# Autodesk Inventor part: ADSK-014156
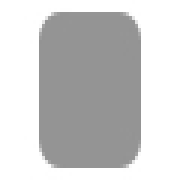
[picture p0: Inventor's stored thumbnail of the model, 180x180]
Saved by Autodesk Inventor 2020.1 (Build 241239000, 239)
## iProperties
Created: 2019-01
Part Number: ADSK-014156
Material: Stahl, weich
Document SubType Name: Modeling
Designer: lutzd
Language: de-DE
Size Designation: 5 x 39,384472 x 39,384472
Categories: <MemberInstance><Categories><Category DisplayName="Sonstige Bauteile" InternalName="5aa15e00-363f-49f2-933f-16f664388e3f" Mnemonic="OTHER"><Category DisplayName
Mass: 60.0398 g
Surface Area: 38.0412 cm^2
Volume: 7.64838 cm^3
Density: 7.85 g/cm^3
Appearance: Halbpoliert
IsCustomPart: 1
Title: end cap
Author: lutzd
Revision Number: -
Dimensions: 39,4x39,4x5 mm
Mass: 0,06 kg
DocNumber: ADSK-014156
Folder: 01 - Themengebiete\Simplification\01 - Packaging machine\
VDS_Category: 3D Komponenten
VDS_NumSchm: Autodesk
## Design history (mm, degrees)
sketch "Sketch1"
  geometry: L1 (0, 20.175)-(0, -21.446); L2 (-20.203, 0)-(20.169, 0); L3 (-19.692, 19.692)-(19.692, 19.692); L4 (19.692, 19.692)-(19.692, -19.692); L5 (19.692, -19.692)-(-19.692, -19.692); L6 (-19.692, -19.692)-(-19.692, 19.692); 1 further point
  constraints: 12 end point, 2 horizontal, 2 parallel, 2 point on line, 1 perpendicular, 1 vertical
  dimensions: "d0" = 39.38447 distance between parallel lines of L5 L3 (= height); "d1" = 19.69224 distance between parallel lines of L2 L3 (= 0.5 x height); "d2" = 39.38447 distance between parallel lines of L6 L4 (= width); "d3" = 19.69224 distance between parallel lines of L6 L1 (= 0.5 x width)
extrude "Extrusion1" new body sketch "Sketch1" distance "d4" = 5 (= thickness); taper "d5" = 0 deg
fillet "Fillet1" dims "d6" = 5 (= fillet), "d7" = 0, "fillet" = 5 [user parameter; used in 1 equation term]
chamfer "Chamfer1" distance "d8" = 0 (computed from chamfer); stored, may be unused: second distance "d9" = 2, angle "d10" = 45 deg; dims "d11" = 0, "chamfer" = 0 [user parameter; used in 1 equation term]
body "Solid1"
other parameters: "thickness" = 5 [user parameter; used in 1 equation term], "width" = 39.38447 [user parameter; used in 2 equation terms], "height" = 39.38447 [user parameter; used in 2 equation terms]
